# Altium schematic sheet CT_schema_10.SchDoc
size 564 x 458 mm
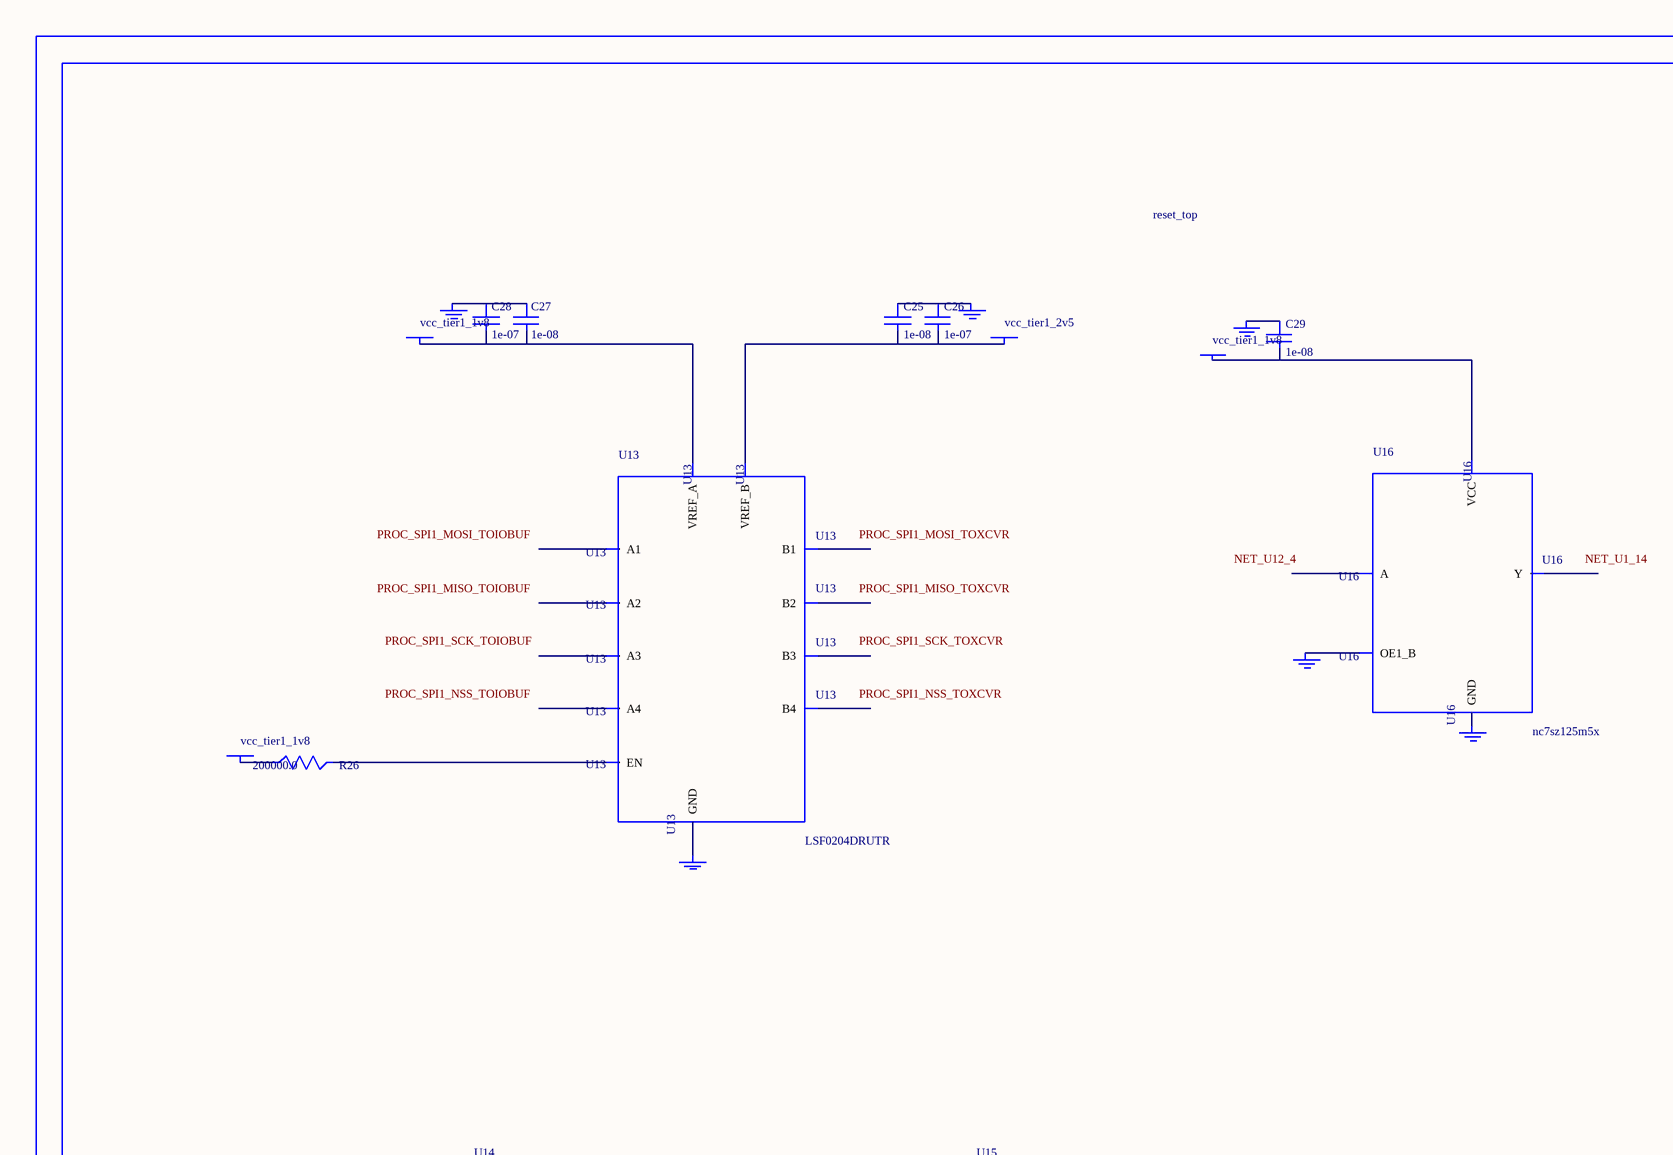
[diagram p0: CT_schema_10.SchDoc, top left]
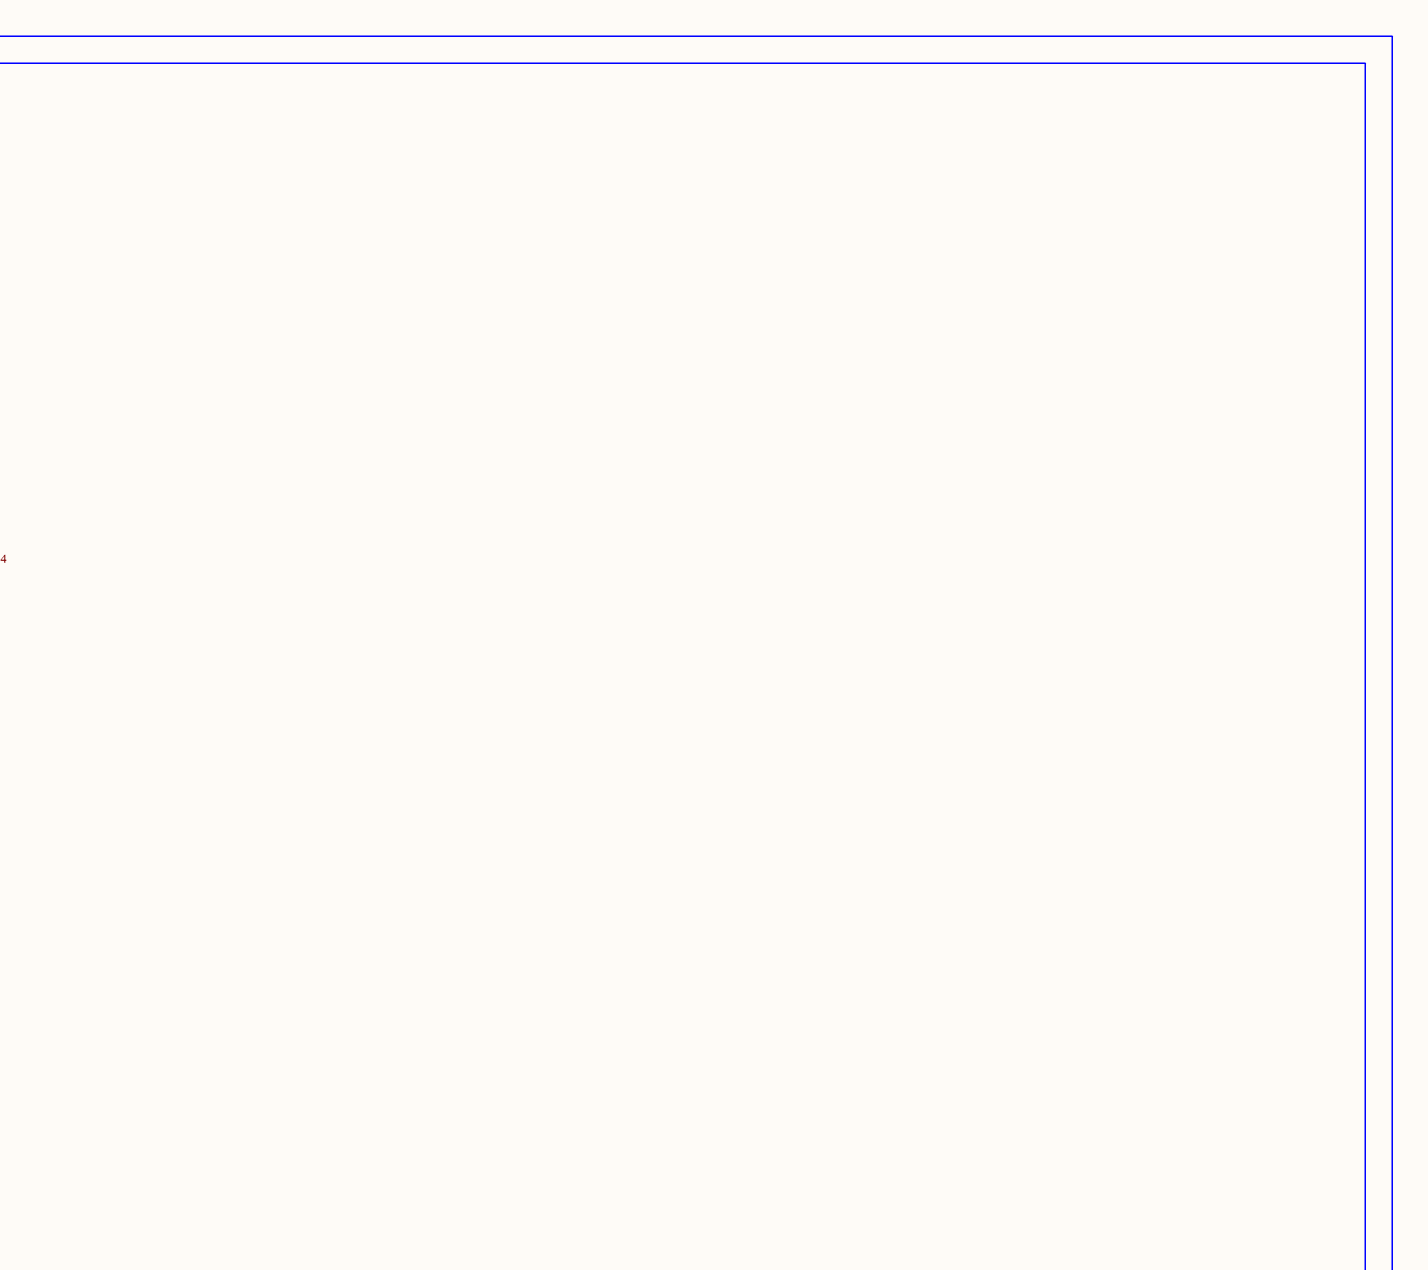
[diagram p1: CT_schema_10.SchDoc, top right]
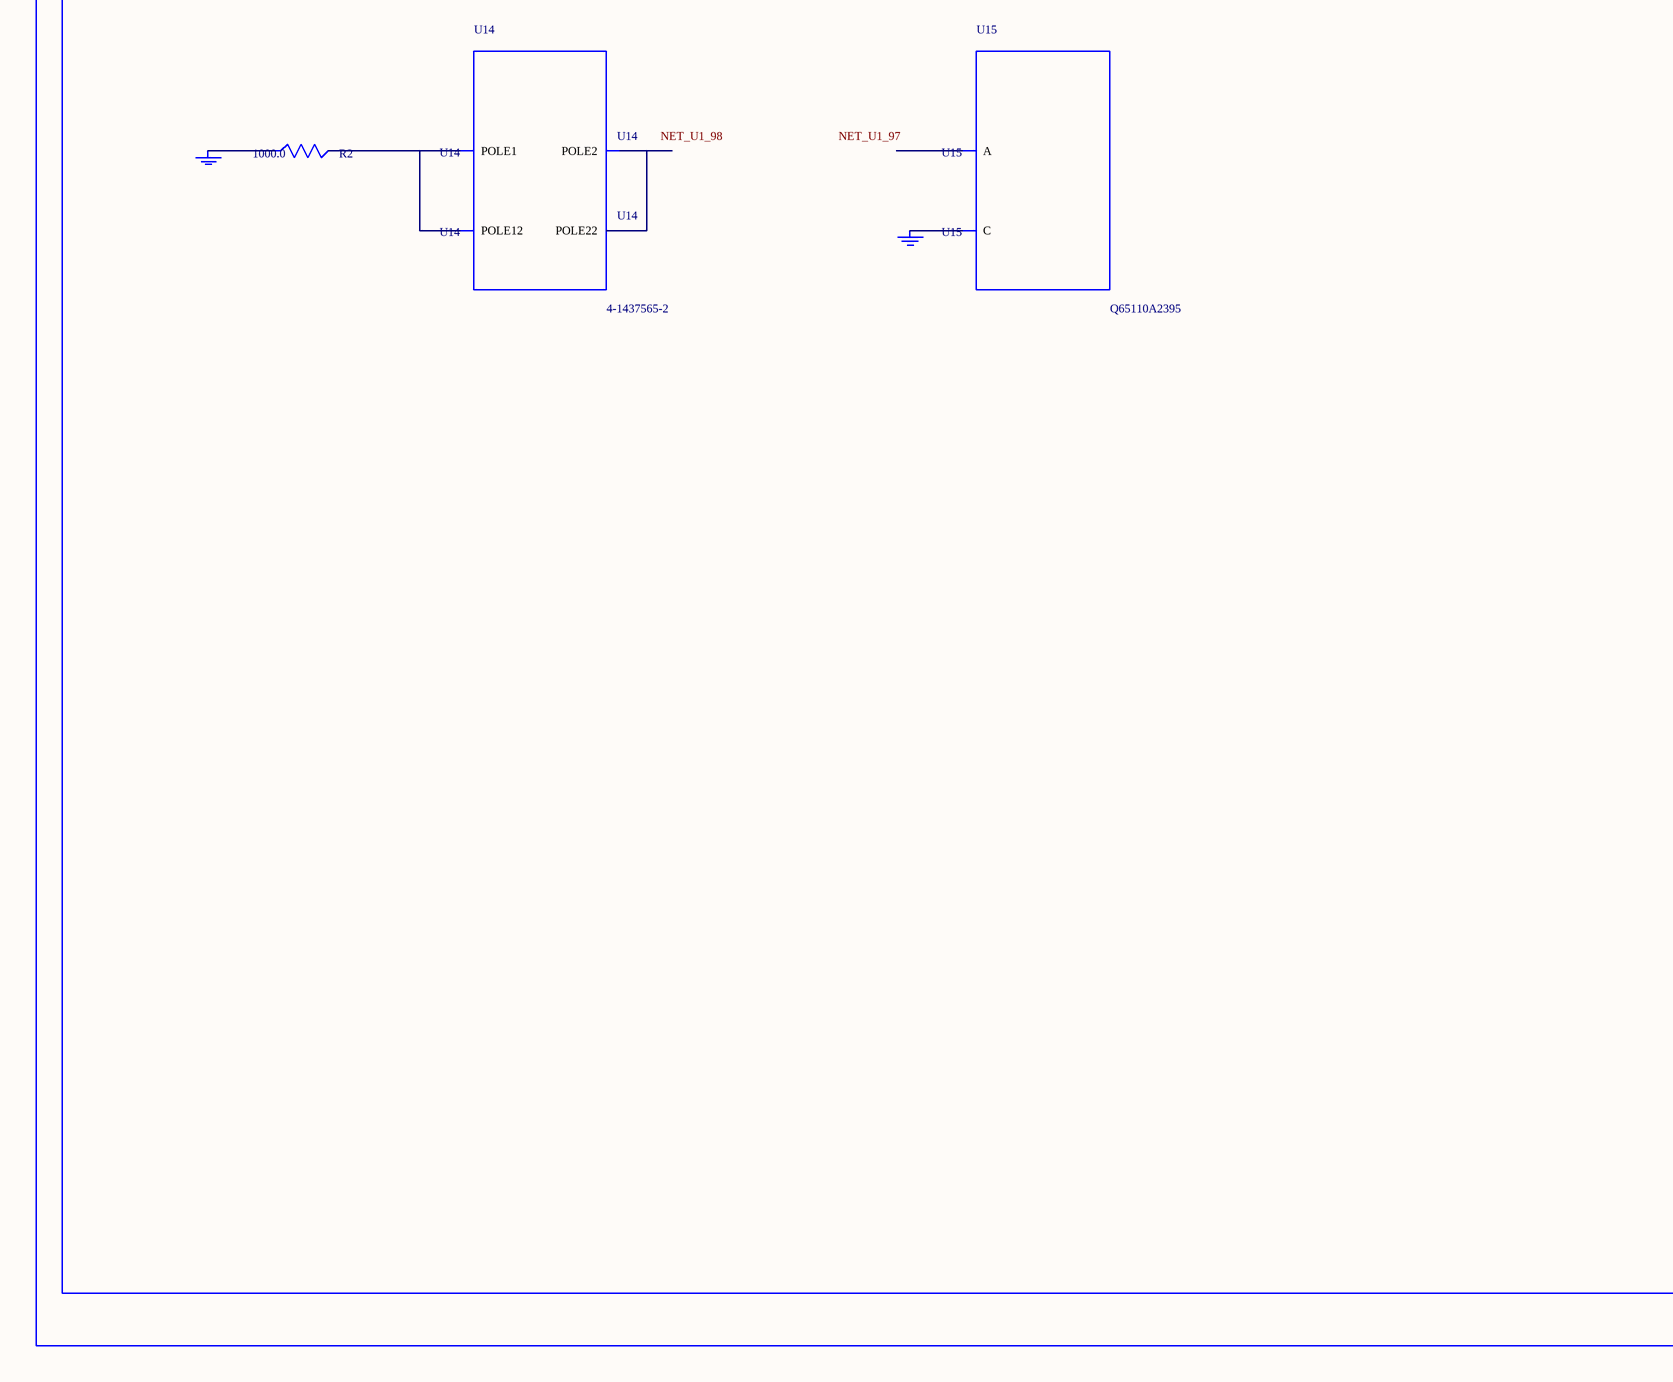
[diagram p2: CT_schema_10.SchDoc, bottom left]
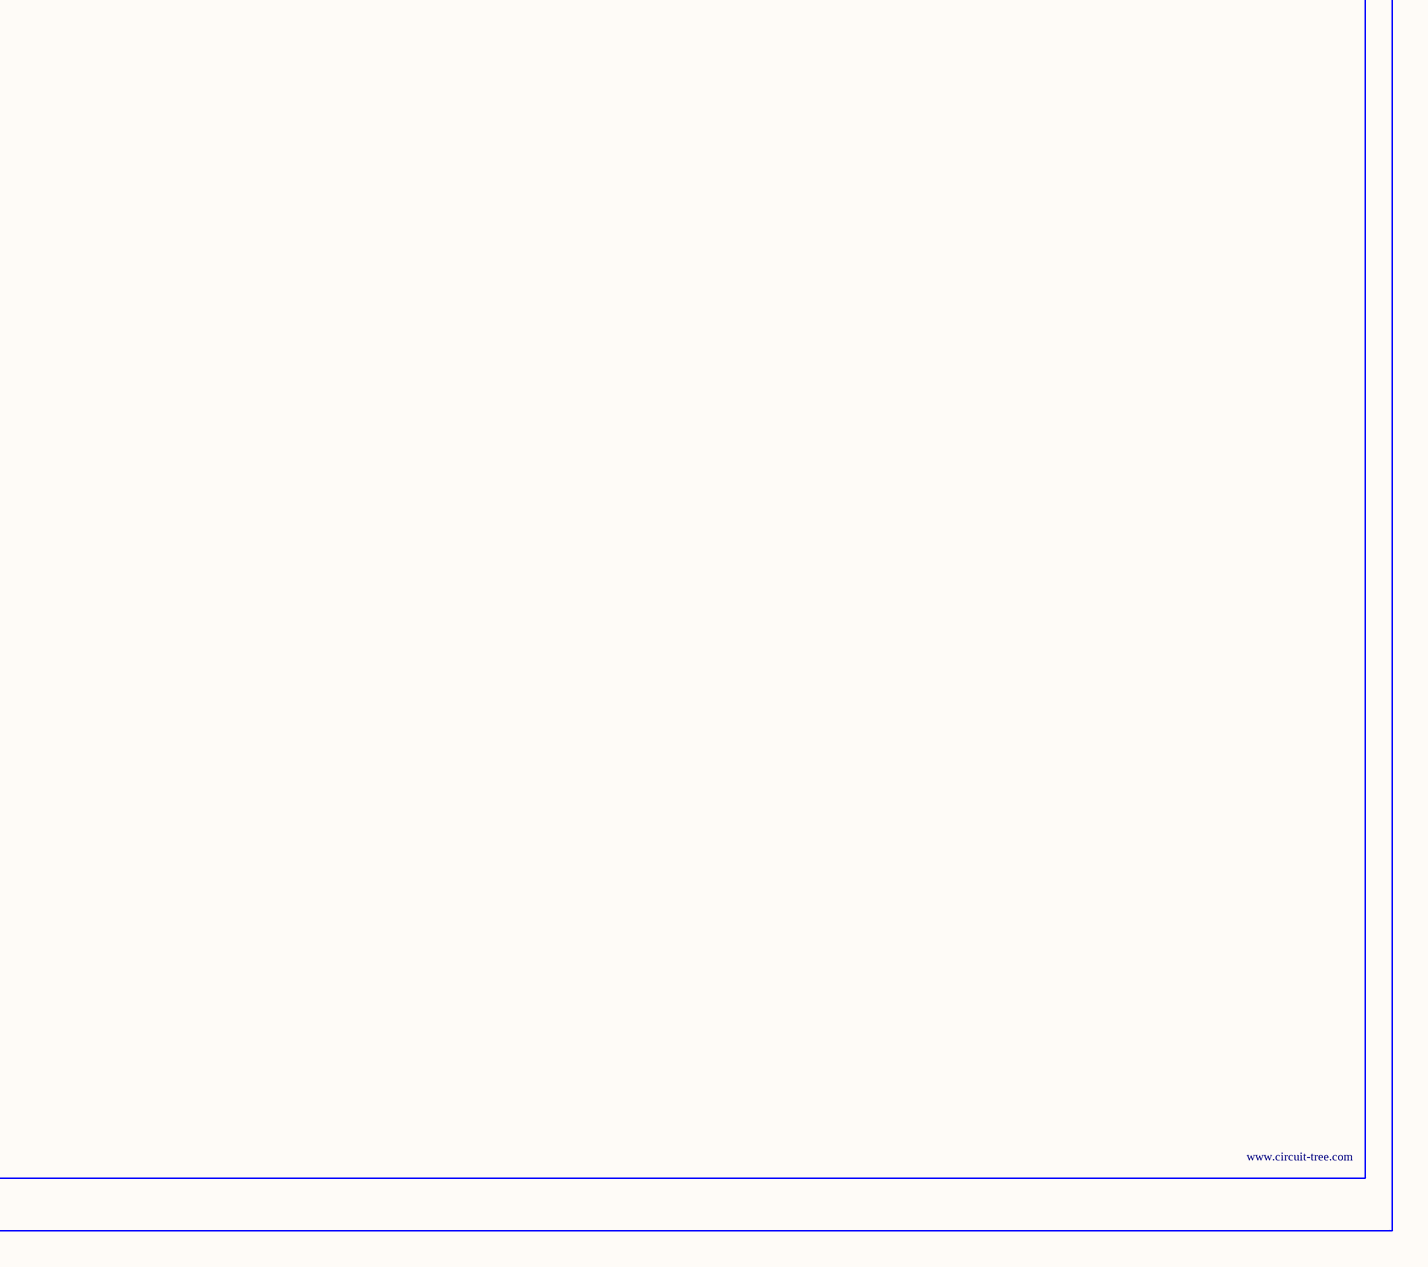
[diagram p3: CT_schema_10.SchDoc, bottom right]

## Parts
BORDER9  (no value)
C25  1e-08  [C0402]
C26  1e-07  [C0402]
C27  1e-08  [C0402]
C28  1e-07  [C0402]
C29  1e-08  [C0402]
GND_INSTANCE_9_0  (no value)
GND_INSTANCE_9_1  (no value)
GND_INSTANCE_9_2  (no value)
GND_INSTANCE_9_3  (no value)
GND_INSTANCE_9_4  (no value)
GND_INSTANCE_9_5  (no value)
GND_INSTANCE_9_6  (no value)
GND_INSTANCE_9_7  (no value)
POWER_INSTANCE_9_0  vcc_tier1_1v8
POWER_INSTANCE_9_1  vcc_tier1_2v5
POWER_INSTANCE_9_2  vcc_tier1_1v8
POWER_INSTANCE_9_3  vcc_tier1_1v8
R2  1000.0  [R0603]
R26  200000.0  [R0603]
U13  LSF0204DRUTR  [RUT0012A]
U14  4-1437565-2  [SW_4-1437565-2]
U15  Q65110A2395  [LGM67K-G1J2-24-Z]
U16  nc7sz125m5x  [NC7SZ125M5X]

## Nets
NetC25_1: C25.1 C26.1 GND_INSTANCE_9_1.0(GND)
NetC25_2: C25.2 C26.2 POWER_INSTANCE_9_1.0(PWR) U13.11(VREF_B)
NetC27_1: C27.1 C28.1 GND_INSTANCE_9_0.0(GND)
NetC27_2: C27.2 C28.2 POWER_INSTANCE_9_0.0(PWR) U13.1(VREF_A)
NetC29_1: C29.1 GND_INSTANCE_9_5.0(GND)
NetC29_2: C29.2 POWER_INSTANCE_9_3.0(PWR) U16.5(VCC)
NetGND_INSTANCE_9_2_0: GND_INSTANCE_9_2.0(GND) U13.6(GND)
NetGND_INSTANCE_9_3_0: GND_INSTANCE_9_3.0(GND) R2.1
NetGND_INSTANCE_9_4_0: GND_INSTANCE_9_4.0(GND) U15.C
NetGND_INSTANCE_9_6_0: GND_INSTANCE_9_6.0(GND) U16.1(OE1_B)
NetGND_INSTANCE_9_7_0: GND_INSTANCE_9_7.0(GND) U16.3(GND)
NetPOWER_INSTANCE_9_2_0: POWER_INSTANCE_9_2.0(PWR) R26.1
NetR2_2: R2.2 U14.1(POLE1) U14.2(POLE12)
NetR26_2: R26.2 U13.12(EN)
NetU14_3: U14.3(POLE2) U14.4(POLE22)

Not connected (* = marked no-connect by the designer): U13 2(A1) 3(A2) 4(A3) 5(A4) 7(B4) 8(B3) 9(B2) 10(B1); U15 A; U16 2(A) 4(Y)

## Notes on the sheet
- Labels drawn without touching a wire or pin: NET_U1_14, NET_U1_97, NET_U1_98, NET_U12_4, PROC_SPI1_MISO_TOIOBUF, PROC_SPI1_MISO_TOXCVR, PROC_SPI1_MOSI_TOIOBUF, PROC_SPI1_MOSI_TOXCVR, PROC_SPI1_NSS_TOIOBUF, PROC_SPI1_NSS_TOXCVR, PROC_SPI1_SCK_TOIOBUF, PROC_SPI1_SCK_TOXCVR

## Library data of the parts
BORDER9 = BORDER_PAGE9
C25 C27 C29 = C0402C103K3RAC
C26 C28 = C0402C104K3RACTU
GND_INSTANCE_9_0-GND_INSTANCE_9_7 = GND
POWER_INSTANCE_9_0-POWER_INSTANCE_9_3 = PWR
R2 = RC0603JR-071KL
R26 = RC0603JR-07200KL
